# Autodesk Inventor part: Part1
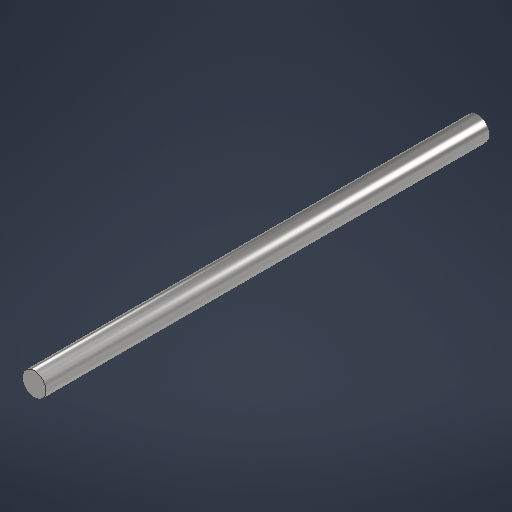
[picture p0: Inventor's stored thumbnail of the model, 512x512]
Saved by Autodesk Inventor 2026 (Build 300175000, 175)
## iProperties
Created: 2026-03
Part Number: Part1
Material: Stainless Steel
Document SubType Name: Modeling
Designer: Мельников Ю.С.
Density: 8 g/cm^3
Appearance: Semi-Polished
Author: Мельников Ю.С.
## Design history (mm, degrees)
sketch "Sketch1"
  geometry: C1 r 4 at (0, 0); 1 further point
  constraints: 1 centre point, 1 coincident
  dimensions: "d0" = 8 diameter of C1
extrude "Extrusion1" new body sketch "Sketch1" distance "d1" = 150; taper "d2" = 0 deg
body "Solid1"
other parameters: "sa_0" = 20000
